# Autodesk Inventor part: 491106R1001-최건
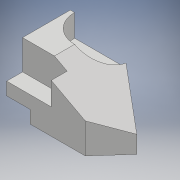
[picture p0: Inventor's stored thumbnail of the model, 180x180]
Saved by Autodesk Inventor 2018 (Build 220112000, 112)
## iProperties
Created: 2019-11
Part Number: 491106R1001-최건
Material: 일반
Document SubType Name: Modeling
Designer: USER
Density: 1 g/cm^3
Appearance: 기본값
Author: USER
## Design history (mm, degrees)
sketch "스케치1"
  geometry: L1 (-31.947, 31.906)-(65.053, 31.906); L2 (65.053, 31.906)-(65.053, -28.094); L3 (65.053, -28.094)-(-31.947, -28.094); L4 (-31.947, -28.094)-(-31.947, 31.906); 1 further point
  constraints: 8 end point, 2 parallel, 1 horizontal, 1 perpendicular
  dimensions: "d0" = 60 distance of L3.end L1.start; "d1" = 97 distance of L1.start L1.end
extrude "돌출1" new body sketch "스케치1" distance "d2" = 52; taper "d3" = 0 deg
sketch "스케치2"
  geometry: L1 (0, 0)-(0, 52) reference; L2 (0, 52)-(97, 52) reference; L3 (97, 52)-(97, 0) reference; L4 (97, 0)-(0, 0) reference; L5 (0, 12)-(22, 12); L6 (22, 12)-(22, 0); L7 (0, 0)-(97, 0) reference; L8 (97, 52)-(0, 52) reference; L9 (56.534, 52)-(97, 32.283); L10 (0, 0)-(0, 52) reference; L11 (0, 12)-(0, 0); L12 (0, 0)-(22, 0); 1 further point
  constraints: 10 end point, 4 point on line, 1 collinear, 1 horizontal, 1 perpendicular, 1 vertical
  dimensions: "d4" = 22 distance of L5.start L5.end; "d5" = 12 distance of L5.end L6.end
extrude "돌출2" cut sketch "스케치2" distance "d6" = 45; taper "d7" = 0 deg
sketch "스케치3"
  geometry: L1 (-31.947, -28.094)-(-31.947, 31.906) reference; L2 (-31.947, 31.906)-(65.053, 31.906) reference; L3 (65.053, 31.906)-(65.053, -28.094) reference; L4 (65.053, -28.094)-(-31.947, -28.094) reference; L5 (-31.947, -28.094)-(65.053, -28.094) reference; L6 (42.053, -28.094)-(65.053, -2.55); L7 (65.053, -28.094)-(65.053, 31.906) reference; L8 (65.053, -2.55)-(19.328, 31.906); L9 (42.053, -28.094)-(65.053, -28.094); L10 (65.053, -28.094)-(65.053, -2.55); L11 (65.053, -2.55)-(65.053, 31.906); 1 further point
  constraints: 10 end point, 3 point on line, 2 collinear
  dimensions: "d8" = 132 deg angle of L4 L6; "d9" = 23 distance of L3.end L6.start; "d10" = 95 deg angle of L6 L8
extrude "돌출3" cut sketch "스케치3" extent not by distance; stored distance "d11" = 21; taper "d12" = 0 deg
sketch "스케치4"
  geometry: L1 (19.328, 31.906)-(65.053, -2.55) reference; L2 (65.053, -2.55)-(65.053, -28.094) reference; L3 (65.053, -28.094)-(-31.947, -28.094) reference; L4 (-31.947, -28.094)-(-31.947, 31.906) reference; L5 (-31.947, 31.906)-(19.328, 31.906) reference; L6 (65.053, -2.55)-(42.053, -28.094); L7 (65.053, -2.55)-(65.053, -28.094) reference; L8 (42.053, -28.094)-(65.053, -28.094); L9 (65.053, -28.094)-(65.053, -2.55); 1 further point
  constraints: 6 end point, 1 collinear, 1 horizontal, 1 point on line
  dimensions: "d13" = 23 distance of L2.end L6.end
extrude "돌출4" cut sketch "스케치4" extent not by distance; stored distance "d14" = 21; taper "d15" = 0 deg
sketch "스케치5"
  geometry: 1 further point
sketch "스케치6"
  geometry: L1 (65.053, -2.55)-(42.053, -28.094) reference; L2 (42.053, -28.094)-(-31.947, -28.094) reference; L3 (-31.947, -28.094)-(-31.947, 31.906) reference; L4 (-31.947, 31.906)-(19.328, 31.906) reference; L5 (19.328, 31.906)-(65.053, -2.55) reference; L6 (-31.947, 31.906)-(19.328, 31.906) reference; C1 r 26 at (-1.947, 31.906); 1 further point
  constraints: 1 centre point, 1 point on line
  dimensions: "d16" = 52 diameter of C1; "d17" = 30 distance of L3.end C1.centre
extrude "돌출5" cut sketch "스케치6" distance "d18" = 21; taper "d19" = 0 deg
sketch "스케치7"
  geometry: L1 (22, -12)-(22, 0) reference; L2 (22, 0)-(0, 0) reference; L3 (0, 0)-(0, 40) reference; L4 (0, 40)-(74, 40) reference; L5 (74, 40)-(74, -12) reference; L6 (74, -12)-(22, -12) reference; L7 (0, -12)-(0, 40) reference; L8 (0, 40)-(42, 40); L9 (42, 40)-(42, 12); L10 (42, 12)-(0, 12); L11 (0, 12)-(0, 40); 1 further point
  constraints: 8 end point, 2 parallel, 1 horizontal, 1 perpendicular
  dimensions: "d20" = 42 distance of L9.end L10.end; "d21" = 28 distance of L8.end L9.end
extrude "돌출6" cut sketch "스케치7" distance "d22" = 15; taper "d23" = 0 deg
sketch "스케치8"
  geometry: L1 (22, -12)-(22, 0) reference; L2 (22, 0)-(0, 0) reference; L3 (0, 0)-(0, 12) reference; L4 (0, 12)-(42, 12) reference; L5 (42, 12)-(42, 40) reference; L6 (42, 40)-(74, 40) reference; L7 (74, 40)-(74, -12) reference; L8 (74, -12)-(22, -12) reference; L9 (74, 40)-(97, 40) reference; L10 (97, -12)-(97, 40) reference; L11 (0, 40)-(42, 40) reference; L12 (4, 40)-(55.778, 40) reference; L13 (30, 40)-(97, 4.375); L14 (30, 40)-(107.053, 40); L15 (107.053, 40)-(107.053, 4.375); L16 (107.053, 4.375)-(97, 4.375); 1 further point
  constraints: 8 end point, 3 point on line, 2 perpendicular
  dimensions: "d24" = 28 deg angle of L6 L13; "d25" = 30 distance of L11.start L13.start
extrude "돌출7" cut sketch "스케치8" distance "d26" = 60; taper "d27" = 0 deg
node "솔리드1"
node "절단 모서리 투영1"
node "절단 모서리 투영2"
node "절단 모서리 투영3"
node "절단 모서리 투영4"
node "절단 모서리 투영5"
node "절단 모서리 투영6"
